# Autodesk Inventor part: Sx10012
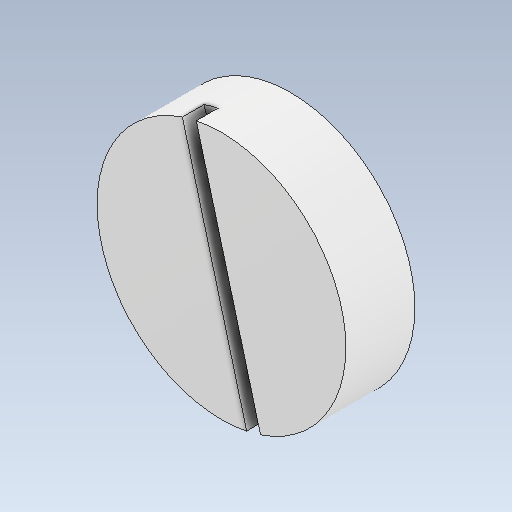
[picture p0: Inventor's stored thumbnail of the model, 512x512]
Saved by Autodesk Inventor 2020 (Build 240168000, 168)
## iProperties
Created: 2021-02
Part Number: Sx10012
Material: Generico
Document SubType Name: Modeling
Designer: zambolin
Density: 1 g/cm^3
Appearance: Default
Author: zambolin
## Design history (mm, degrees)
feature "Solido2"
node "Solido1"
